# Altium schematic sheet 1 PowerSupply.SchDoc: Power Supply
size A4
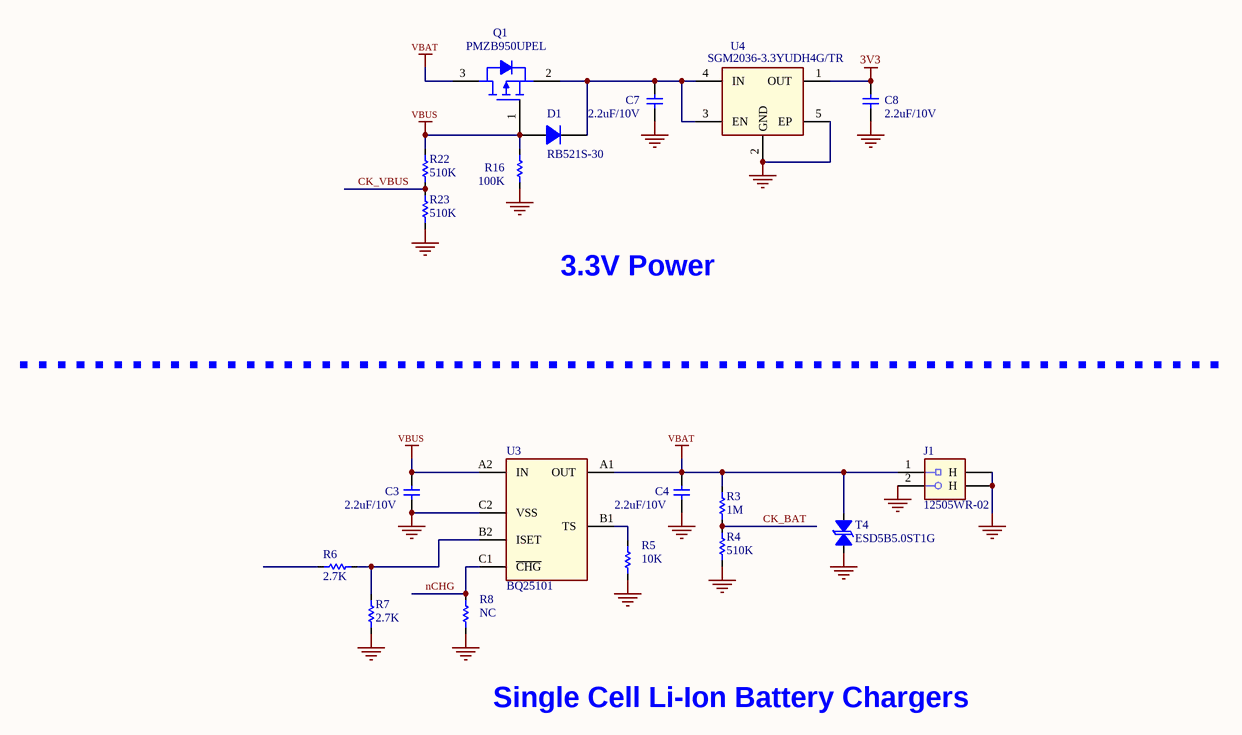
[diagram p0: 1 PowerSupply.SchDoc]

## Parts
C3  2.2uF/10V  [CAP 0402/1005]
C4  2.2uF/10V  [CAP 0402/1005]
C7  2.2uF/10V  [CAP 0402/1005]
C8  2.2uF/10V  [CAP 0402/1005]
D1  RB521S-30  [SOD523]
J1  12505WR-02  [12505WR-02]
Q1  PMZB950UPEL  [SOT883-3 /DFN985X585X50-3N]
R3  1M  [RES 0402/1005]
R4  510K  [RES 0402/1005]
R5  10K  [RES 0402/1005]
R6  2.7K  [RES 0402/1005]
R7  2.7K  [RES 0402/1005]
R8  NC  [RES 0402/1005]
R16  100K  [RES 0402/1005]
R22  510K  [RES 0402/1005]
R23  510K  [RES 0402/1005]
T4  ESD5B5.0ST1G  [SOD523]
U3  BQ25101  [BGA6 C40P2X3_90x160]
U4  SGM2036-3.3YUDH4G/TR  [UTDFN-4 1x1]

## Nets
3V3: C8.2 U4.1(OUT)
GND: C3.1 C4.1 C7.1 C8.1 J1.2 J1.H R4.1 R5.2 R7.2 R8.1 R16.2 R23.1 T4.1 U3.C2(VSS) U4.2(GND) U4.5(EP)
VBAT: C4.2 J1.1 Q1.3(D) R3.2 T4.2 U3.A1(OUT)
VBUS: C3.2 D1.2(A) Q1.1(G) R16.1 R22.2 U3.A2(IN)
CK_BAT: R3.1 R4.2
CK_VBUS: R22.1 R23.2
nCHG: R8.2 U3.C1(~{CHG})
NetC7_2: C7.2 D1.1(K) Q1.2(S) U4.3(EN) U4.4(IN)
NetR5_1: R5.1 U3.B1(TS)
NetR6_1: R6.1 R7.1 U3.B2(ISET)

Not connected (* = marked no-connect by the designer): R6 2

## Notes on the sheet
- 3.3V Power
- Single Cell Li-Ion Battery Chargers

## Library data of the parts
C3 C4 C7 C8 = Cap: Capacitor MLCC
D1 = Diode_MMBD4148: Diode
J1 = CON/2P/Guide
Q1 = MOSFET P-CH: MOSFET-P channel
R3-R8 R16 R22 R23 = Res1_1: Resistor
T4 = TVS Diode: ESD Diode, Bi-direction, SOD-523
U3 = BQ25101_DSBGA_6_BQ25101_DSBGA_6: bq2510x 250-mA Single Cell Li-Ion Battery Chargers, 1-mA Termination, 75-nA Battery / Leakage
